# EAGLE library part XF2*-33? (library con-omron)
OMRON FPC Connector Source : http://www.omron.com/ecb/products/pdf/fpc.pdf
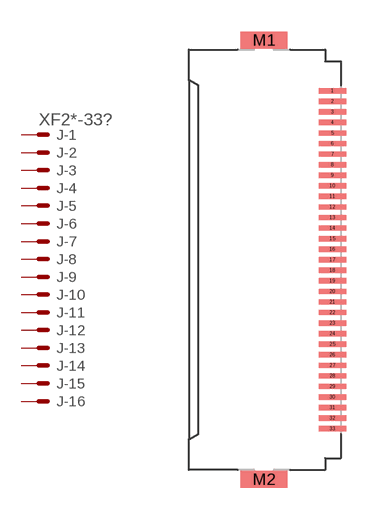
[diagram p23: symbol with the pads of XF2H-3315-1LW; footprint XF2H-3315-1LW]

Designator prefix J; gates -1=PV -2=P -3=P -4=P -5=P -6=P -7=P -8=P -9=P -10=P -11=P -12=P -13=P -14=P -15=P -16=P -17=P -18=P -19=P -20=P -21=P -22=P -23=P -24=P -25=P -26=P -27=P -28=P -29=P -30=P -31=P -32=P -33=P

## XF2H-3315-1LW (MPN: XF2H-3315-1LW; OC_FARNELL: unknown; OC_NEWARK: 12J5146)  [XF2H-3315-1LW]
1  -1:MSV  pas
2  -2:MS  pas
3  -3:MS  pas
4  -4:MS  pas
5  -5:MS  pas
6  -6:MS  pas
7  -7:MS  pas
8  -8:MS  pas
9  -9:MS  pas
10  -10:MS  pas
11  -11:MS  pas
12  -12:MS  pas
13  -13:MS  pas
14  -14:MS  pas
15  -15:MS  pas
16  -16:MS  pas
17  -17:MS  pas
18  -18:MS  pas
19  -19:MS  pas
20  -20:MS  pas
21  -21:MS  pas
22  -22:MS  pas
23  -23:MS  pas
24  -24:MS  pas
25  -25:MS  pas
26  -26:MS  pas
27  -27:MS  pas
28  -28:MS  pas
29  -29:MS  pas
30  -30:MS  pas
31  -31:MS  pas
32  -32:MS  pas
33  -33:MS  pas

## Footprint XF2H-3315-1LW (pad centres in mm)
Standard Rotary Backlock Type (0.5 mm-pitch) Source : http://www.omron.com/ecb/products/pdf/fpc.pdf
smd 1.3 x 0.25: 1 3.175,8; 2 3.175,7.5; 3 3.175,7; 4 3.175,6.5; 5 3.175,6; 6 3.175,5.5; 7 3.175,5; 8 3.175,4.5; 9 3.175,4; 10 3.175,3.5; 11 3.175,3; 12 3.175,2.5; 13 3.175,2; 14 3.175,1.5; 15 3.175,1; 16 3.175,0.5; 17 3.175,0; 18 3.175,-0.5; 19 3.175,-1; 20 3.175,-1.5; 21 3.175,-2; 22 3.175,-2.5; 23 3.175,-3; 24 3.175,-3.5; 25 3.175,-4; 26 3.175,-4.5; 27 3.175,-5; 28 3.175,-5.5; 29 3.175,-6; 30 3.175,-6.5; 31 3.175,-7; 32 3.175,-7.5; 33 3.175,-8
smd 2.2 x 0.8: M1 -0.075,10.4; M2 -0.075,-10.4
